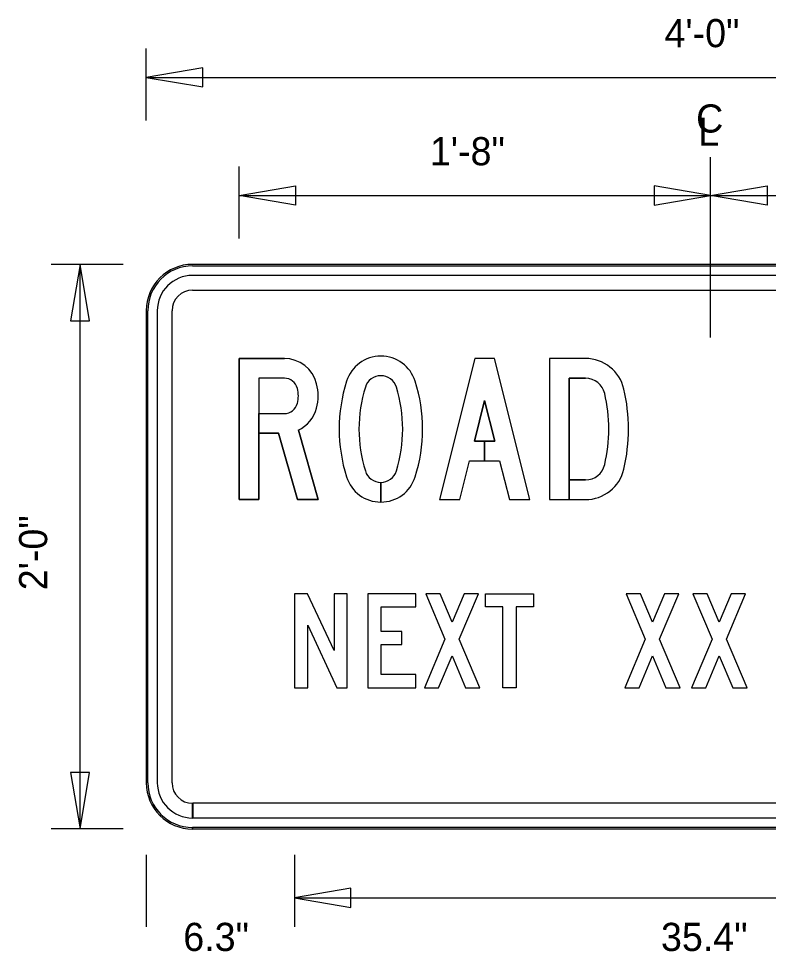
# Model space of a CAD drawing. Extents: x 0 to 770, y 0 to 495.
# Drawn here: x 10 to 103.2, y 365.5 to 481.4 of the extents above; entities that cross this region are included whole.
import ezdxf

# ---------------------------------------------------------------- set-up
doc = ezdxf.new("R2010")
doc.units = 0
for name, color, linetype in [('Dimension', 7, 'Continuous'), ('GSColorFill', 7, 'Continuous'), ('GSDims', 7, 'Continuous'), ('SheetLines_dp', 7, 'Continuous'), ('TextStructures', 7, 'Continuous')]:
    doc.layers.add(name, color=color, linetype=linetype)

msp = doc.modelspace()

# ---------------------------------------------------------------- linework, layer by layer
at = {"layer": 'Dimension'}
for points in [[(25.84, 474.11), (32.86, 472.93), (32.86, 475.3)], [(37.38, 459.44), (44.39, 460.63), (44.39, 458.25)], [(96.02, 459.44), (89.01, 460.63), (89.01, 458.25)], [(96.02, 459.44), (103.04, 460.63), (103.04, 458.25)], [(17.6, 450.87), (16.41, 443.85), (18.79, 443.85)], [(17.6, 380.69), (18.79, 387.7), (16.41, 387.7)], [(44.27, 372.12), (51.29, 370.93), (51.29, 373.31)]]:
    msp.add_lwpolyline(points, close=True, dxfattribs=at)
at = {"layer": 'GSColorFill'}
for p, q in [((160.45, 450.87), (31.6, 450.87)), ((31.6, 450.69), (160.45, 450.69)), ((160.45, 449.5), (31.6, 449.5)), ((31.6, 447.67), (160.45, 447.67)), ((25.84, 445.11), (25.84, 386.44)), ((26.02, 386.44), (26.02, 445.11)), ((27.21, 445.11), (27.21, 386.44)), ((29.04, 386.44), (29.04, 445.11)), ((43.01, 439.17), (37.38, 439.17)), ((43.01, 436.72), (43.01, 436.72)), ((43.01, 432.33), (43.01, 432.33)), ((43.01, 432.33), (43.01, 432.33)), ((55.01, 423.78), (55.01, 421.32)), ((55.01, 421.32), (55.01, 423.78)), ((55.01, 423.78), (55.01, 421.32)), ((55.01, 421.32), (55.01, 423.78)), ((78.43, 424.08), (80.45, 424.08)), ((80.45, 424.08), (78.43, 424.08)), ((80.45, 424.08), (78.43, 424.08)), ((80.45, 421.63), (80.45, 421.63)), ((31.6, 382.06), (31.6, 383.89)), ((160.45, 383.89), (31.62, 383.89)), ((31.62, 383.89), (31.62, 382.06)), ((31.62, 382.06), (160.45, 382.06)), ((31.6, 380.69), (31.6, 380.87)), ((160.45, 380.87), (31.6, 380.87)), ((31.6, 380.87), (31.6, 380.69)), ((31.6, 380.69), (160.45, 380.69))]:
    msp.add_line(p, q, dxfattribs=at)
for points in [[(37.38, 439.17), (37.38, 421.63), (39.83, 421.63), (39.83, 429.87), (42.3, 429.87), (44.65, 421.63), (47.2, 421.63), (44.75, 430.26)], [(43.01, 436.72), (39.83, 436.72), (39.83, 421.63), (37.38, 421.63), (37.38, 439.17), (43.01, 439.17)], [(43.01, 436.72), (39.83, 436.72), (39.83, 421.63), (37.38, 421.63), (37.38, 439.17), (43.01, 439.17)], [(80.45, 439.17), (75.98, 439.17), (75.98, 421.63), (80.45, 421.63)], [(80.45, 439.17), (75.98, 439.17), (75.98, 421.63), (78.43, 421.63), (78.43, 436.72), (80.45, 436.72)], [(80.45, 439.17), (75.98, 439.17), (75.98, 421.63), (78.43, 421.63), (78.43, 436.72), (80.45, 436.72)], [(43.01, 436.72), (39.83, 436.72), (39.83, 432.33), (43.01, 432.33)], [(80.45, 436.72), (78.43, 436.72), (78.43, 424.08)], [(44.75, 430.26), (47.2, 421.63), (44.65, 421.63), (42.3, 429.87), (39.83, 429.87), (39.83, 432.33), (43.01, 432.33)], [(44.75, 430.26), (47.2, 421.63), (44.65, 421.63), (42.3, 429.87), (39.83, 429.87), (39.83, 432.33), (43.01, 432.33)], [(78.43, 424.08), (78.43, 421.63), (80.45, 421.63)], [(78.43, 424.08), (78.43, 421.63), (80.45, 421.63)]]:
    msp.add_lwpolyline(points, dxfattribs=at)
for points in [[(66.03, 426.45), (69.78, 426.45), (70.99, 421.63), (73.52, 421.63), (69.13, 439.17), (66.68, 439.17), (62.29, 421.63), (64.82, 421.63)], [(67.91, 428.91), (66.64, 428.91), (67.91, 433.96), (69.17, 428.91), (67.91, 428.91), (67.91, 426.45), (69.78, 426.45), (70.99, 421.63), (73.52, 421.63), (69.13, 439.17), (66.68, 439.17), (62.29, 421.63), (64.82, 421.63), (66.03, 426.45), (67.91, 426.45)], [(67.91, 428.91), (66.64, 428.91), (67.91, 433.96), (69.17, 428.91), (67.91, 428.91), (67.91, 426.45), (69.78, 426.45), (70.99, 421.63), (73.52, 421.63), (69.13, 439.17), (66.68, 439.17), (62.29, 421.63), (64.82, 421.63), (66.03, 426.45), (67.91, 426.45)], [(69.17, 428.91), (67.91, 433.96), (66.64, 428.91)], [(49.54, 398.23), (50.82, 398.23), (50.82, 409.93), (49.19, 409.93), (49.19, 402.86), (45.89, 409.93), (44.27, 409.93), (44.27, 398.23), (45.91, 398.23), (45.91, 406.01)], [(49.54, 398.23), (50.82, 398.23), (50.82, 409.93), (49.19, 409.93), (49.19, 402.86), (45.89, 409.93), (44.27, 409.93), (44.27, 398.23), (45.91, 398.23), (45.91, 406.01)], [(49.54, 398.23), (50.82, 398.23), (50.82, 409.93), (49.19, 409.93), (49.19, 402.86), (45.89, 409.93), (44.27, 409.93), (44.27, 398.23), (45.91, 398.23), (45.91, 406.01)], [(55.04, 399.87), (55.04, 403.61), (57.6, 403.61), (57.6, 405.25), (55.04, 405.25), (55.04, 408.29), (59.36, 408.29), (59.36, 409.93), (53.4, 409.93), (53.4, 398.23), (59.36, 398.23), (59.36, 399.87)], [(55.04, 399.87), (55.04, 403.61), (57.6, 403.61), (57.6, 405.25), (55.04, 405.25), (55.04, 408.29), (59.36, 408.29), (59.36, 409.93), (53.4, 409.93), (53.4, 398.23), (59.36, 398.23), (59.36, 399.87)], [(55.04, 399.87), (55.04, 403.61), (57.6, 403.61), (57.6, 405.25), (55.04, 405.25), (55.04, 408.29), (59.36, 408.29), (59.36, 409.93), (53.4, 409.93), (53.4, 398.23), (59.36, 398.23), (59.36, 399.87)], [(63.87, 402.19), (65.54, 398.23), (67.32, 398.23), (64.76, 404.29), (67.14, 409.93), (65.36, 409.93), (63.87, 406.39), (62.37, 409.93), (60.59, 409.93), (62.98, 404.29), (60.42, 398.23), (62.19, 398.23)], [(63.87, 402.19), (65.54, 398.23), (67.32, 398.23), (64.76, 404.29), (67.14, 409.93), (65.36, 409.93), (63.87, 406.39), (62.37, 409.93), (60.59, 409.93), (62.98, 404.29), (60.42, 398.23), (62.19, 398.23)], [(63.87, 402.19), (65.54, 398.23), (67.32, 398.23), (64.76, 404.29), (67.14, 409.93), (65.36, 409.93), (63.87, 406.39), (62.37, 409.93), (60.59, 409.93), (62.98, 404.29), (60.42, 398.23), (62.19, 398.23)], [(70.18, 408.29), (68.02, 408.29), (68.02, 409.93), (73.99, 409.93), (73.99, 408.29), (71.82, 408.29), (71.82, 398.23), (70.18, 398.23)], [(70.18, 408.29), (68.02, 408.29), (68.02, 409.93), (73.99, 409.93), (73.99, 408.29), (71.82, 408.29), (71.82, 398.23), (70.18, 398.23)], [(70.18, 408.29), (68.02, 408.29), (68.02, 409.93), (73.99, 409.93), (73.99, 408.29), (71.82, 408.29), (71.82, 398.23), (70.18, 398.23)], [(88.78, 402.19), (90.45, 398.23), (92.23, 398.23), (89.67, 404.29), (92.06, 409.93), (90.28, 409.93), (88.78, 406.39), (87.29, 409.93), (85.51, 409.93), (87.89, 404.29), (85.33, 398.23), (87.11, 398.23)], [(88.78, 402.19), (90.45, 398.23), (92.23, 398.23), (89.67, 404.29), (92.06, 409.93), (90.28, 409.93), (88.78, 406.39), (87.29, 409.93), (85.51, 409.93), (87.89, 404.29), (85.33, 398.23), (87.11, 398.23)], [(88.78, 402.19), (90.45, 398.23), (92.23, 398.23), (89.67, 404.29), (92.06, 409.93), (90.28, 409.93), (88.78, 406.39), (87.29, 409.93), (85.51, 409.93), (87.89, 404.29), (85.33, 398.23), (87.11, 398.23)], [(97.09, 402.19), (98.76, 398.23), (100.54, 398.23), (97.98, 404.29), (100.36, 409.93), (98.58, 409.93), (97.09, 406.39), (95.59, 409.93), (93.81, 409.93), (96.2, 404.29), (93.64, 398.23), (95.41, 398.23)], [(97.09, 402.19), (98.76, 398.23), (100.54, 398.23), (97.98, 404.29), (100.36, 409.93), (98.58, 409.93), (97.09, 406.39), (95.59, 409.93), (93.81, 409.93), (96.2, 404.29), (93.64, 398.23), (95.41, 398.23)], [(97.09, 402.19), (98.76, 398.23), (100.54, 398.23), (97.98, 404.29), (100.36, 409.93), (98.58, 409.93), (97.09, 406.39), (95.59, 409.93), (93.81, 409.93), (96.2, 404.29), (93.64, 398.23), (95.41, 398.23)]]:
    msp.add_lwpolyline(points, close=True, dxfattribs=at)
for centre, radius, start, end in [((31.6, 445.11), 5.76, 90, 180), ((31.6, 445.11), 5.57, 90, 180), ((31.6, 445.11), 4.39, 90, 180), ((31.6, 445.11), 2.56, 90, 180), ((55.01, 435.01), 4.47, 17.3283, 162.6717), ((55.01, 435.01), 4.47, 17.3283, 162.6717), ((55.01, 435.01), 4.47, 17.3283, 162.6717), ((43.01, 435.05), 4.12, 13.8865, 90), ((43.01, 435.05), 4.12, 13.8865, 90), ((43.01, 435.05), 4.12, 13.8865, 90), ((80.45, 434.26), 4.91, 13.109, 90), ((80.45, 434.26), 4.91, 13.109, 90), ((80.45, 434.26), 4.91, 13.109, 90), ((43.01, 435.05), 1.67, 13.8865, 90), ((43.01, 435.05), 1.67, 13.8865, 90), ((43.01, 435.05), 1.67, 13.8865, 90), ((40.89, 434.52), 6.32, 346.1135, 13.8865), ((40.89, 434.52), 6.32, 346.1135, 13.8865), ((40.89, 434.52), 6.32, 346.1135, 13.8865), ((69.77, 430.4), 19.94, 162.6717, 197.3283), ((69.77, 430.4), 19.94, 162.6717, 197.3283), ((69.77, 430.4), 19.94, 162.6717, 197.3283), ((55.01, 435.01), 2.02, 17.3283, 162.6717), ((55.01, 435.01), 2.02, 17.3283, 162.6717), ((55.01, 435.01), 2.02, 17.3283, 162.6717), ((40.25, 430.4), 19.94, 342.6717, 17.3283), ((40.25, 430.4), 19.94, 342.6717, 17.3283), ((40.25, 430.4), 19.94, 342.6717, 17.3283), ((80.45, 434.26), 2.46, 13.109, 90), ((80.45, 434.26), 2.46, 13.109, 90), ((80.45, 434.26), 2.46, 13.109, 90), ((40.89, 434.52), 3.86, 346.1135, 13.8865), ((40.89, 434.52), 3.86, 346.1135, 13.8865), ((40.89, 434.52), 3.86, 346.1135, 13.8865), ((69.77, 430.4), 17.48, 162.6717, 197.3283), ((69.77, 430.4), 17.48, 162.6717, 197.3283), ((69.77, 430.4), 17.48, 162.6717, 197.3283), ((40.25, 430.4), 17.48, 342.6717, 17.3283), ((40.25, 430.4), 17.48, 342.6717, 17.3283), ((40.25, 430.4), 17.48, 342.6717, 17.3283), ((63.87, 430.4), 19.48, 346.891, 13.109), ((63.87, 430.4), 19.48, 346.891, 13.109), ((63.87, 430.4), 19.48, 346.891, 13.109), ((63.87, 430.4), 21.93, 346.891, 13.109), ((63.87, 430.4), 21.93, 346.891, 13.109), ((63.87, 430.4), 21.93, 346.891, 13.109), ((43.01, 434), 1.67, 270, 346.1135), ((43.01, 434), 1.67, 270, 346.1135), ((43.01, 434), 1.67, 270, 346.1135), ((43.01, 434), 4.12, 294.8221, 346.1135), ((43.01, 434), 4.12, 294.8221, 346.1135), ((43.01, 434), 4.12, 294.8221, 346.1135), ((80.45, 426.54), 2.46, 270, 346.891), ((80.45, 426.54), 2.46, 270, 346.891), ((80.45, 426.54), 2.46, 270, 346.891), ((55.01, 425.79), 4.47, 197.3283, 342.6717), ((55.01, 425.79), 4.47, 197.3283, 270), ((55.01, 425.79), 4.47, 197.3283, 270), ((55.01, 425.79), 2.02, 197.3283, 342.6717), ((55.01, 425.79), 2.02, 197.3283, 270), ((55.01, 425.79), 2.02, 197.3283, 270), ((55.01, 425.79), 2.02, 270.0249, 342.6717), ((55.01, 425.79), 2.02, 270.0249, 342.6717), ((55.01, 425.79), 4.47, 270.0112, 342.6717), ((55.01, 425.79), 4.47, 270.0112, 342.6717), ((80.45, 426.54), 4.91, 270, 346.891), ((80.45, 426.54), 4.91, 270, 346.891), ((80.45, 426.54), 4.91, 270, 346.891), ((31.6, 386.44), 5.76, 180, 270), ((31.6, 386.44), 5.57, 180, 270), ((31.6, 386.44), 4.39, 180, 270), ((31.6, 386.44), 2.56, 180, 270)]:
    msp.add_arc(centre, radius, start, end, dxfattribs=at)
at = {"layer": 'GSDims'}
for p, q in [((25.84, 468.74), (25.84, 477.7)), ((25.84, 474.11), (166.21, 474.11)), ((37.38, 454.07), (37.38, 463.02)), ((37.38, 459.44), (96.02, 459.44)), ((96.02, 459.44), (154.67, 459.44)), ((22.97, 450.87), (14.02, 450.87)), ((17.6, 380.69), (17.6, 450.87)), ((22.97, 380.69), (14.02, 380.69)), ((25.84, 377.49), (25.84, 368.54)), ((44.27, 377.49), (44.27, 368.54)), ((44.27, 372.12), (147.77, 372.12))]:
    msp.add_line(p, q, dxfattribs=at)
at = {"layer": 'SheetLines_dp'}
msp.add_line((96.02, 441.79), (96.02, 464.2), dxfattribs=at)

# ---------------------------------------------------------------- texts
at = {"layer": 'TextStructures'}
for s, p in [('4\'-0"', (90.28, 477.87)), ('C', (94.21, 467.26)), ('L', (94.47, 465.61)), ('1\'-8"', (61.11, 463.19)), ('6.3"', (30.44, 365.52)), ('35.4"', (89.84, 365.52))]:
    msp.add_text(s, height=3.5, dxfattribs=at).set_placement(p)
msp.add_text('2\'-0"', height=3.5, rotation=90, dxfattribs=at).set_placement((13.52, 410.36))

doc.saveas('drawing.dxf')
